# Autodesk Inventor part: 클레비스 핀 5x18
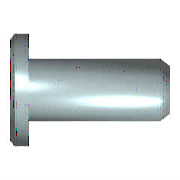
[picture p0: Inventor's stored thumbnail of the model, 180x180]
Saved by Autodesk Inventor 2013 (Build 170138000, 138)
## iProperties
IsCustomPart: 0
Created: 2012-02
Part Number: 클레비스 핀 5x18
Material: 강철
Description: 머리가 있는 클레비스 핀
Document SubType Name: Modeling
Standard: ISO 2341
Designer: mduedu
Standard Revision: Second edition 1986-11-01
Standards Organization: ISO
Language: ko-KR
Size Designation: A - 5 x 18
Categories: <MemberInstance><Categories><Category DisplayName="조임쇠" InternalName="e4da775c-781d-43d5-af7c-5136215cf5a6" Mnemonic="FSTN"><Category DisplayName="핀" InternalNa
Density: 7.85 g/cm^3
Author: mduedu
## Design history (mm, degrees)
sketch "스케치1"
  geometry: L1 (-1.6, 0)-(-1.6, 4); L2 (-1.6, 4)-(0, 4); L3 (0, 4)-(0, 2.5); L4 (0, 2.5)-(18, 2.5); L5 (18, 2.5)-(18, 0); L6 (-1.6, 0)-(18, 0); L7 (-4, 0)-(17, 0) reference; L8 (0, -0.5)-(0, 3) reference
  constraints: 12 end point, 3 parallel, 2 collinear, 2 perpendicular, 1 vertical
  dimensions: "d0" = 1.6 distance of L1.end L2.end (= KOH); "d1" = 18 distance of L3.end L4.end (= NLG); "d2" = 5 diameter of L4 L6 (= NND); "d3" = 8 diameter of L2 L6 (= KOD)
revolve "본체" sketch "스케치1" stored, may be unused: angle "d5" = 90 deg
node "작업 평면1"
sketch "스케치2"
  geometry: C1 r 2.5 at (0, 0) reference; C2 r 1.95 at (0, 0); 1 further point
  constraints: 1 centre point, 1 coincident
  dimensions: "d16" = 3.9 diameter of C2
extrude "돌출1" cut sketch "스케치2" distance "d17" = 0.6; taper "d18" = 0 deg
body "Solid1"
chamfer "모따기1" distance "d7" = 2 (= PHH1); stored, may be unused: angle "d8" = 30 deg (= FAWI1), second distance "d12" = 2 (= PHH1)
chamfer "모따기2" distance "d4" = 1 (= PHH2); stored, may be unused: angle "d6" = 45 deg (= FAWI2), second distance "d13" = 1 (= PHH2)
other parameters: "NLG" = 18 [user parameter; used in 1 equation term], "KOH" = 1.6 [user parameter; used in 1 equation term], "KOD" = 8 [user parameter; used in 1 equation term], "NND" = 5 [user parameter; used in 1 equation term], "FAWI1" = 30 deg [user parameter; used in 1 equation term], "FAWI2" = 45 deg [user parameter; used in 1 equation term], "PHH2" = 1 [user parameter; used in 2 equation terms], "PHH1" = 2 [user parameter; used in 2 equation terms], "d9" = 0, "d10" = 0, "d14" = 0, "d15" = 13
